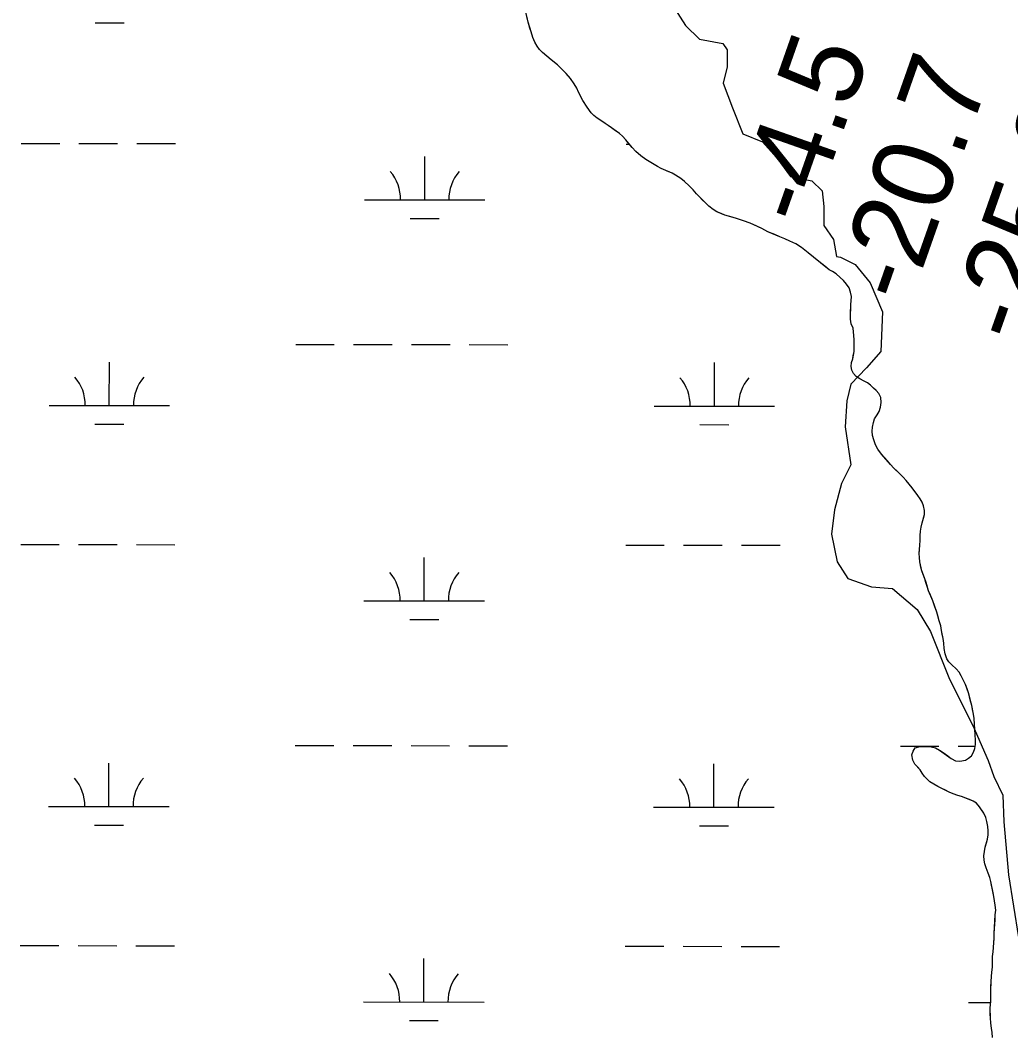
# Model space of a CAD drawing. Extents: x 3148686 to 3186545, y 916144 to 941516.
# Drawn here: x 3161687 to 3162509, y 935379 to 936220 of the extents above; entities that cross this region are included whole.
import ezdxf

# ---------------------------------------------------------------- set-up
doc = ezdxf.new("R2010")
doc.units = 0
for name, color, linetype in [('V-RIVR-EDGE', 7, 'Continuous'), ('V-RIVR-RANG', 7, 'Continuous'), ('V-SITE-VEGE', 7, 'Continuous'), ('V-WETL-SWMP', 7, 'Continuous')]:
    doc.layers.add(name, color=color, linetype=linetype)

msp = doc.modelspace()

# ---------------------------------------------------------------- linework, layer by layer
at = {"layer": 'V-RIVR-EDGE'}
for points in [[(3162222.05, 936242.3), (3162239.01, 936215.31), (3162250.68, 936203.93), (3162270.17, 936200.34), (3162273.71, 936195.01), (3162273.67, 936180.83), (3162270.45, 936167.36), (3162278.2, 936146.78)], [(3162278.2, 936146.78), (3162286.65, 936125.48), (3162302.95, 936118.7), (3162314.97, 936105.55), (3162326.28, 936089.92), (3162344, 936086.33), (3162352.49, 936078.15), (3162353.88, 936065.03), (3162353.84, 936049.43), (3162361.96, 936037.71), (3162364.41, 936023.52), (3162367.6, 936023.16), (3162380, 936017.1), (3162392.37, 936001.82), (3162402.59, 935977.68), (3162401.09, 935944.71), (3162389.36, 935931.26), (3162376.21, 935917.82), (3162372.98, 935904), (3162371.51, 935882.37), (3162376.4, 935850.8), (3162368.56, 935835.22), (3162362.83, 935813.6), (3162360.3, 935793.4), (3162364.85, 935770.34), (3162373.68, 935756.49), (3162393.52, 935749.7), (3162410.89, 935748.24), (3162431.42, 935730.81), (3162442.36, 935712.7), (3162458.22, 935672.95), (3162477.63, 935634.6), (3162490.32, 935605.49), (3162494.9, 935592.36), (3162502.31, 935576.74), (3162503.32, 935554.76), (3162507.11, 935510.78), (3162515.49, 935458.63)]]:
    msp.add_lwpolyline(points, dxfattribs=at)
at = {"layer": 'V-SITE-VEGE'}
for p, q in [((3162108.6, 936217.93), (3162106.4, 936227.37)), ((3162111.12, 936209.87), (3162108.6, 936217.93)), ((3162112.45, 936205.15), (3162111.12, 936209.87)), ((3162114.25, 936201.34), (3162112.45, 936205.15)), ((3162116.19, 936197.98), (3162114.25, 936201.34)), ((3162118.15, 936195.39), (3162116.19, 936197.98)), ((3162120.56, 936192.79), (3162118.15, 936195.39)), ((3162127.65, 936186.81), (3162120.56, 936192.79)), ((3162132.93, 936182.52), (3162127.65, 936186.81)), ((3162140.16, 936175.48), (3162132.93, 936182.52)), ((3162143.77, 936171.2), (3162140.16, 936175.48)), ((3162146.78, 936166.92), (3162143.77, 936171.2)), ((3162148.88, 936163.11), (3162146.78, 936166.92)), ((3162150.37, 936159.91), (3162148.88, 936163.11)), ((3162153.96, 936153.05), (3162150.37, 936159.91)), ((3162157.56, 936147.4), (3162153.96, 936153.05)), ((3162160.87, 936142.82), (3162157.56, 936147.4)), ((3162162.98, 936140.68), (3162160.87, 936142.82)), ((3162165.99, 936138.22), (3162162.98, 936140.68)), ((3162175.06, 936132.23), (3162165.99, 936138.22)), ((3162184.27, 936125.63), (3162175.06, 936132.23)), ((3162186.99, 936123.33), (3162184.27, 936125.63)), ((3162189.54, 936120.43), (3162186.99, 936123.33)), ((3162194.81, 936114.01), (3162189.54, 936120.43)), ((3162197.97, 936110.79), (3162194.81, 936114.01)), ((3162202.04, 936107.12), (3162197.97, 936110.79)), ((3162206.27, 936104.05), (3162202.04, 936107.12)), ((3162215.8, 936098.2), (3162206.27, 936104.05)), ((3162218.97, 936096.66), (3162215.8, 936098.2)), ((3162228.2, 936092.64), (3162218.97, 936096.66)), ((3162230.92, 936091.1), (3162228.2, 936092.64)), ((3162235.31, 936088.34), (3162230.92, 936091.1)), ((3162238.32, 936085.88), (3162235.31, 936088.34)), ((3162242.25, 936082.21), (3162238.32, 936085.88)), ((3162245.56, 936078.84), (3162242.25, 936082.21)), ((3162248.12, 936075.63), (3162245.56, 936078.84)), ((3162258.51, 936065.38), (3162248.12, 936075.63)), ((3162261.99, 936062.62), (3162258.51, 936065.38)), ((3162265.01, 936060.77), (3162261.99, 936062.62)), ((3162271.82, 936057.99), (3162265.01, 936060.77)), ((3162274.7, 936057.05), (3162271.82, 936057.99)), ((3162281.52, 936055.18), (3162274.7, 936057.05)), ((3162287.12, 936053.31), (3162281.52, 936055.18)), ((3162292.72, 936051.14), (3162287.12, 936053.31)), ((3162302.41, 936046.82), (3162292.72, 936051.14)), ((3162307.55, 936044.19), (3162302.41, 936046.82)), ((3162317.39, 936039.87), (3162307.55, 936044.19)), ((3162321.48, 936038.32), (3162317.39, 936039.87)), ((3162325.71, 936036.46), (3162321.48, 936038.32)), ((3162330.56, 936034.15), (3162325.71, 936036.46)), ((3162335.39, 936031.07), (3162330.56, 936034.15)), ((3162340.82, 936026.78), (3162335.39, 936031.07)), ((3162351.08, 936018.35), (3162340.82, 936026.78)), ((3162358.33, 936012.67), (3162351.08, 936018.35)), ((3162361.2, 936011.28), (3162358.33, 936012.67)), ((3162364.22, 936009.13), (3162361.2, 936011.28)), ((3162370.26, 936003.62), (3162364.22, 936009.13)), ((3162372.81, 936000.56), (3162370.26, 936003.62)), ((3162374.77, 935997.66), (3162372.81, 936000.56)), ((3162376.1, 935994.01), (3162374.77, 935997.66)), ((3162376.84, 935990.51), (3162376.1, 935994.01)), ((3162375.97, 935976.24), (3162376.32, 935983.38)), ((3162376.32, 935983.38), (3162376.84, 935990.51)), ((3162376.08, 935971.53), (3162375.97, 935976.24)), ((3162376.66, 935967.73), (3162376.08, 935971.53)), ((3162378.15, 935964.23), (3162376.66, 935967.73)), ((3162378.49, 935961.16), (3162378.15, 935964.23)), ((3162379, 935954.66), (3162378.49, 935961.16)), ((3162379.04, 935948.25), (3162379, 935954.66)), ((3162377.85, 935938.6), (3162378.92, 935944.82)), ((3162378.92, 935944.82), (3162379.04, 935948.25)), ((3162376.59, 935932.48), (3162376.81, 935935.64)), ((3162377.22, 935929.32), (3162376.59, 935932.48)), ((3162376.81, 935935.64), (3162377.85, 935938.6)), ((3162378.5, 935926.52), (3162377.22, 935929.32)), ((3162380.8, 935924.18), (3162378.5, 935926.52)), ((3162383.67, 935922.12), (3162380.8, 935924.18)), ((3162387.37, 935920.32), (3162383.67, 935922.12)), ((3162390.14, 935918.72), (3162387.37, 935920.32)), ((3162392.54, 935916.85), (3162390.14, 935918.72)), ((3162395.22, 935914.5), (3162392.54, 935916.85)), ((3162397.43, 935912.35), (3162395.22, 935914.5)), ((3162399.46, 935910.1), (3162397.43, 935912.35)), ((3162401.19, 935906.56), (3162399.46, 935910.1)), ((3162399.8, 935894.96), (3162400.95, 935898.58)), ((3162400.95, 935898.58), (3162401.54, 935902.47)), ((3162401.54, 935902.47), (3162401.19, 935906.56)), ((3162395.95, 935888.96), (3162398.02, 935892.38)), ((3162398.02, 935892.38), (3162399.8, 935894.96)), ((3162393.92, 935878.85), (3162394.22, 935882.1)), ((3162394.22, 935882.1), (3162395, 935885.99)), ((3162395, 935885.99), (3162395.95, 935888.96)), ((3162394.26, 935875.04), (3162393.92, 935878.85)), ((3162395.26, 935871.41), (3162394.26, 935875.04)), ((3162396.8, 935867.49), (3162395.26, 935871.41)), ((3162398.82, 935863.67), (3162396.8, 935867.49)), ((3162401.76, 935859.75), (3162398.82, 935863.67)), ((3162409.31, 935851.05), (3162401.76, 935859.75)), ((3162412.07, 935848.06), (3162409.31, 935851.05)), ((3162417.33, 935843.09), (3162412.07, 935848.06)), ((3162419.81, 935840.47), (3162417.33, 935843.09)), ((3162422.12, 935837.95), (3162419.81, 935840.47)), ((3162424.6, 935834.86), (3162422.12, 935837.95)), ((3162427.09, 935831.69), (3162424.6, 935834.86)), ((3162431.77, 935825.33), (3162427.09, 935831.69)), ((3162433.7, 935822.53), (3162431.77, 935825.33)), ((3162435.44, 935819.73), (3162433.7, 935822.53)), ((3162436.63, 935816.94), (3162435.44, 935819.73)), ((3162437.53, 935813.03), (3162436.63, 935816.94)), ((3162435.41, 935802.64), (3162437.32, 935809.5)), ((3162437.32, 935809.5), (3162437.53, 935813.03)), ((3162434.05, 935795.87), (3162434.63, 935799.21)), ((3162434.63, 935799.21), (3162435.41, 935802.64)), ((3162433.71, 935788.07), (3162433.74, 935792.07)), ((3162433.74, 935792.07), (3162434.05, 935795.87)), ((3162433.07, 935777.31), (3162433.4, 935784.08)), ((3162433.4, 935784.08), (3162433.71, 935788.07)), ((3162433.14, 935774.05), (3162433.07, 935777.31)), ((3162433.48, 935770.24), (3162433.14, 935774.05)), ((3162435.28, 935762.8), (3162433.48, 935770.24)), ((3162438.65, 935753.21), (3162435.28, 935762.8)), ((3162440.82, 935746.22), (3162438.65, 935753.21)), ((3162444.19, 935737.93), (3162440.82, 935746.22)), ((3162447.56, 935728.52), (3162444.19, 935737.93)), ((3162449.64, 935721.36), (3162447.56, 935728.52)), ((3162450.81, 935717.17), (3162449.64, 935721.36)), ((3162451.43, 935713.45), (3162450.81, 935717.17)), ((3162452.87, 935706.75), (3162451.43, 935713.45)), ((3162453.39, 935702.84), (3162452.87, 935706.75)), ((3162453.82, 935698.38), (3162453.39, 935702.84)), ((3162454.53, 935693.92), (3162453.82, 935698.38)), ((3162455.9, 935690.01), (3162454.53, 935693.92)), ((3162457.55, 935687.3), (3162455.9, 935690.01)), ((3162459.94, 935684.96), (3162457.55, 935687.3)), ((3162463.72, 935681.49), (3162459.94, 935684.96)), ((3162466.12, 935678.78), (3162463.72, 935681.49)), ((3162467.95, 935675.89), (3162466.12, 935678.78)), ((3162469.87, 935671.97), (3162467.95, 935675.89)), ((3162471.33, 935668.53), (3162469.87, 935671.97)), ((3162474.15, 935660.79), (3162471.33, 935668.53)), ((3162476.68, 935651.12), (3162474.15, 935660.79)), ((3162478.11, 935644.14), (3162476.68, 935651.12)), ((3162478.55, 935640.33), (3162478.11, 935644.14)), ((3162479.37, 935626.95), (3162478.55, 935640.33)), ((3162479.61, 935622.39), (3162479.37, 935626.95)), ((3162479.59, 935618.96), (3162479.61, 935622.39)), ((3162426.95, 935610.26), (3162428, 935613.32)), ((3162428, 935613.32), (3162429.78, 935616)), ((3162429.78, 935616), (3162432.67, 935616.91)), ((3162432.67, 935616.91), (3162439.54, 935617.13)), ((3162439.54, 935617.13), (3162442.79, 935617.01)), ((3162442.79, 935617.01), (3162446.59, 935615.96)), ((3162446.59, 935615.96), (3162449.83, 935614.27)), ((3162449.83, 935614.27), (3162459.62, 935607.32)), ((3162476.26, 935609.51), (3162478.14, 935612.47)), ((3162478.14, 935612.47), (3162479.19, 935615.43)), ((3162479.19, 935615.43), (3162479.59, 935618.96)), ((3162427.66, 935605.98), (3162426.95, 935610.26)), ((3162429.4, 935602.63), (3162427.66, 935605.98)), ((3162459.62, 935607.32), (3162463.14, 935605.43)), ((3162463.14, 935605.43), (3162466.76, 935605.12)), ((3162466.76, 935605.12), (3162471.4, 935605.83)), ((3162471.4, 935605.83), (3162473.93, 935607.48)), ((3162473.93, 935607.48), (3162476.26, 935609.51)), ((3162433.91, 935597.76), (3162429.4, 935602.63)), ((3162435.38, 935595.06), (3162433.91, 935597.76)), ((3162437.4, 935592.44), (3162435.38, 935595.06)), ((3162439.52, 935590.01), (3162437.4, 935592.44)), ((3162441.82, 935587.95), (3162439.52, 935590.01)), ((3162448.57, 935583.99), (3162441.82, 935587.95)), ((3162457.92, 935579.28), (3162448.57, 935583.99)), ((3162461.16, 935577.86), (3162457.92, 935579.28)), ((3162465.05, 935576.53), (3162461.16, 935577.86)), ((3162468.1, 935575.67), (3162465.05, 935576.53)), ((3162471.81, 935574.34), (3162468.1, 935575.67)), ((3162477.83, 935571.79), (3162471.81, 935574.34)), ((3162480.51, 935570.28), (3162477.83, 935571.79)), ((3162483.09, 935567.2), (3162480.51, 935570.28)), ((3162486.57, 935561.78), (3162483.09, 935567.2)), ((3162488.31, 935558.24), (3162486.57, 935561.78)), ((3162489.22, 935554.89), (3162488.31, 935558.24)), ((3162489.83, 935550.8), (3162489.22, 935554.89)), ((3162490.08, 935547.27), (3162489.83, 935550.8)), ((3162490.15, 935544.01), (3162490.08, 935547.27)), ((3162487.84, 935533.72), (3162489.75, 935540.3)), ((3162489.75, 935540.3), (3162490.15, 935544.01)), ((3162486.67, 935526.49), (3162487.07, 935530.11)), ((3162487.07, 935530.11), (3162487.84, 935533.72)), ((3162487.02, 935522.86), (3162486.67, 935526.49)), ((3162487.46, 935519.89), (3162487.02, 935522.86)), ((3162488.45, 935516.44), (3162487.46, 935519.89)), ((3162490.19, 935512.25), (3162488.45, 935516.44)), ((3162491.55, 935508.62), (3162490.19, 935512.25)), ((3162492.36, 935505.17), (3162491.55, 935508.62)), ((3162494.96, 935492.71), (3162492.36, 935505.17)), ((3162496.11, 935485.45), (3162494.96, 935492.71)), ((3162496.45, 935481.37), (3162496.11, 935485.45)), ((3162496.14, 935477.65), (3162496.45, 935481.37)), ((3162495.28, 935462.05), (3162496.14, 935477.65)), ((3162495.15, 935458.25), (3162495.28, 935462.05)), ((3162494.42, 935446.92), (3162495.15, 935458.25)), ((3162493.92, 935443.12), (3162494.42, 935446.92)), ((3162493.67, 935434.11), (3162493.9, 935439.96)), ((3162493.9, 935439.96), (3162493.92, 935443.12)), ((3162492.65, 935422.6), (3162493.17, 935430.12)), ((3162493.17, 935430.12), (3162493.67, 935434.11)), ((3162492.3, 935414.15), (3162492.65, 935422.6)), ((3162492.46, 935410.9), (3162492.3, 935414.15)), ((3162492.33, 935405.79), (3162492.46, 935410.9)), ((3162492.01, 935400.32), (3162492.33, 935405.79)), ((3162492.04, 935392.05), (3162492.01, 935400.32)), ((3162492.38, 935387.77), (3162492.04, 935392.05)), ((3162492.9, 935383.68), (3162492.38, 935387.77)), ((3162493.53, 935379.96), (3162492.9, 935383.68)), ((3162493.87, 935375.78), (3162493.53, 935379.96))]:
    msp.add_line(p, q, dxfattribs=at)
at = {"layer": 'V-WETL-SWMP'}
for p, q in [((3161749.49, 936217.34), (3161773.49, 936217.31)), ((3161687.98, 936117.4), (3161719.98, 936117.37)), ((3161735.98, 936117.35), (3161767.98, 936117.32)), ((3161783.98, 936117.3), (3161815.98, 936117.27)), ((3162189.88, 936116.87), (3162192.44, 936116.87)), ((3162022.77, 936070.62), (3162022.81, 936106.62)), ((3161972.77, 936070.67), (3162072.77, 936070.56)), ((3162010.76, 936055.2), (3162034.76, 936055.17)), ((3161915.8, 935950.66), (3161947.8, 935950.63)), ((3161963.8, 935950.61), (3161995.8, 935950.57)), ((3162011.8, 935950.56), (3162043.8, 935950.52)), ((3162059.8, 935950.51), (3162091.8, 935950.47)), ((3161761.16, 935900.08), (3161761.19, 935936.08)), ((3162263.06, 935899.55), (3162263.1, 935935.55)), ((3161711.16, 935900.13), (3161811.16, 935900.03)), ((3162213.06, 935899.6), (3162313.06, 935899.5)), ((3161749.14, 935884.66), (3161773.14, 935884.64)), ((3162251.05, 935884.13), (3162275.05, 935884.11)), ((3161687.63, 935784.73), (3161719.63, 935784.69)), ((3161735.63, 935784.67), (3161767.63, 935784.64)), ((3161783.63, 935784.62), (3161815.63, 935784.59)), ((3162189.53, 935784.2), (3162221.53, 935784.16)), ((3162237.53, 935784.15), (3162269.53, 935784.11)), ((3162285.53, 935784.1), (3162317.53, 935784.06)), ((3162022.42, 935737.94), (3162022.46, 935773.94)), ((3161972.42, 935738), (3162072.42, 935737.89)), ((3162010.4, 935722.52), (3162034.4, 935722.5)), ((3161915.45, 935617.98), (3161947.45, 935617.95)), ((3161963.45, 935617.93), (3161995.45, 935617.9)), ((3162011.45, 935617.88), (3162043.45, 935617.85)), ((3162059.45, 935617.83), (3162091.45, 935617.8)), ((3162417.36, 935617.46), (3162449.36, 935617.42)), ((3162465.36, 935617.4), (3162479.41, 935617.39)), ((3161760.8, 935567.4), (3161760.84, 935603.4)), ((3162262.71, 935566.88), (3162262.75, 935602.88)), ((3161710.8, 935567.46), (3161810.8, 935567.35)), ((3162212.71, 935566.93), (3162312.71, 935566.82)), ((3161748.79, 935551.99), (3161772.79, 935551.96)), ((3162250.7, 935551.46), (3162274.7, 935551.43)), ((3161687.28, 935452.05), (3161719.28, 935452.02)), ((3161735.28, 935452), (3161767.28, 935451.97)), ((3161783.28, 935451.95), (3161815.28, 935451.92)), ((3162189.18, 935451.52), (3162221.18, 935451.49)), ((3162237.18, 935451.47), (3162269.18, 935451.44)), ((3162285.18, 935451.42), (3162317.18, 935451.39)), ((3162022.07, 935405.27), (3162022.11, 935441.27)), ((3161972.07, 935405.32), (3162072.07, 935405.21)), ((3162473.98, 935404.79), (3162492.27, 935404.77)), ((3162010.05, 935389.85), (3162034.05, 935389.82))]:
    msp.add_line(p, q, dxfattribs=at)
msp.add_lwpolyline([(3162493.87, 935375.78), (3162493.53, 935379.96), (3162492.91, 935383.68), (3162492.38, 935387.77), (3162492.04, 935392.05), (3162491.97, 935395.3), (3162492.01, 935400.32), (3162492.33, 935405.79), (3162492.47, 935410.9), (3162492.31, 935414.15), (3162492.42, 935417.68), (3162492.65, 935422.6), (3162492.86, 935426.04), (3162493.17, 935430.12), (3162493.67, 935434.11), (3162493.9, 935439.96), (3162493.92, 935443.12), (3162494.42, 935446.92), (3162494.63, 935450.64), (3162494.84, 935454.07), (3162495.15, 935458.25), (3162495.28, 935462.05), (3162495.49, 935466.05), (3162495.71, 935469.95), (3162495.92, 935473.38), (3162496.14, 935477.65), (3162496.45, 935481.36), (3162496.11, 935485.45), (3162495.58, 935489.17), (3162494.96, 935492.71), (3162494.33, 935495.69), (3162493.7, 935498.66), (3162492.98, 935502.1), (3162492.36, 935505.17), (3162491.55, 935508.62), (3162490.19, 935512.25), (3162488.45, 935516.44), (3162487.46, 935519.89), (3162487.02, 935522.86), (3162486.67, 935526.49), (3162487.07, 935530.11), (3162487.84, 935533.72), (3162488.8, 935537.15), (3162489.75, 935540.3), (3162490.15, 935544.02), (3162490.08, 935547.27), (3162489.83, 935550.8), (3162489.21, 935554.89), (3162488.31, 935558.24), (3162486.57, 935561.78), (3162484.74, 935564.68), (3162483.09, 935567.2), (3162480.51, 935570.28), (3162477.83, 935571.79), (3162474.77, 935573.11), (3162471.81, 935574.34), (3162468.11, 935575.67), (3162465.05, 935576.53), (3162461.16, 935577.86), (3162457.92, 935579.28), (3162454.87, 935580.88), (3162451.81, 935582.3), (3162448.57, 935584), (3162445.15, 935586.07), (3162441.82, 935587.95), (3162439.52, 935590.01), (3162437.4, 935592.44), (3162435.38, 935595.06), (3162433.91, 935597.76), (3162431.61, 935600.2), (3162429.4, 935602.63), (3162427.66, 935605.98), (3162426.95, 935610.26), (3162428, 935613.32), (3162429.78, 935616), (3162432.67, 935616.91), (3162436.01, 935617.07), (3162439.54, 935617.13), (3162442.79, 935617.01), (3162446.59, 935615.96), (3162449.83, 935614.27), (3162452.78, 935612.2), (3162456.67, 935609.47), (3162459.62, 935607.32), (3162463.14, 935605.43), (3162466.75, 935605.12), (3162471.4, 935605.83), (3162473.93, 935607.48), (3162476.26, 935609.51), (3162478.14, 935612.47), (3162479.19, 935615.43), (3162479.59, 935618.96), (3162479.61, 935622.39), (3162479.37, 935626.95), (3162479.13, 935631.59), (3162478.79, 935636.05), (3162478.55, 935640.33), (3162478.11, 935644.14), (3162477.3, 935647.95), (3162476.68, 935651.12), (3162475.41, 935655.86), (3162474.15, 935660.79), (3162472.7, 935664.89), (3162471.33, 935668.53), (3162469.87, 935671.97), (3162467.95, 935675.89), (3162466.12, 935678.78), (3162463.72, 935681.5), (3162459.94, 935684.96), (3162457.55, 935687.3), (3162455.9, 935690.01), (3162454.53, 935693.92), (3162453.82, 935698.38), (3162453.39, 935702.84), (3162452.87, 935706.75), (3162452.15, 935710.38), (3162451.43, 935713.45), (3162450.81, 935717.17), (3162449.64, 935721.36), (3162448.64, 935724.71), (3162447.56, 935728.52), (3162445.92, 935733.09), (3162444.19, 935737.93), (3162442.28, 935742.78), (3162440.82, 935746.22), (3162439.73, 935749.85), (3162438.64, 935753.21), (3162437.65, 935756.19), (3162436.46, 935759.35), (3162435.28, 935762.8), (3162434.47, 935766.06), (3162433.48, 935770.24), (3162433.14, 935774.05), (3162433.07, 935777.31), (3162433.19, 935780.37), (3162433.4, 935784.08), (3162433.71, 935788.08), (3162433.74, 935792.07), (3162434.05, 935795.87), (3162434.64, 935799.21), (3162435.41, 935802.64), (3162436.55, 935806.54), (3162437.32, 935809.5), (3162437.53, 935813.03), (3162436.63, 935816.94), (3162435.44, 935819.73), (3162433.7, 935822.53), (3162431.77, 935825.33), (3162429.29, 935828.7), (3162427.08, 935831.69), (3162424.6, 935834.86), (3162422.12, 935837.95), (3162419.81, 935840.47), (3162417.33, 935843.09), (3162414.56, 935845.71), (3162412.07, 935848.06), (3162409.31, 935851.05), (3162406.64, 935854.04), (3162404.25, 935856.85), (3162401.76, 935859.75), (3162398.82, 935863.67), (3162396.8, 935867.49), (3162395.26, 935871.41), (3162394.26, 935875.04), (3162393.92, 935878.85), (3162394.22, 935882.1), (3162395, 935885.99), (3162395.95, 935888.96), (3162398.02, 935892.38), (3162399.8, 935894.96), (3162400.95, 935898.58), (3162401.53, 935902.47), (3162401.19, 935906.56), (3162399.46, 935910.1), (3162397.43, 935912.35), (3162395.22, 935914.5), (3162392.54, 935916.85), (3162390.14, 935918.72), (3162387.37, 935920.32), (3162383.67, 935922.12), (3162380.8, 935924.18), (3162378.5, 935926.52), (3162377.22, 935929.32), (3162376.6, 935932.48), (3162376.81, 935935.64), (3162377.85, 935938.6), (3162378.34, 935941.57), (3162378.92, 935944.82), (3162379.04, 935948.25), (3162379.06, 935951.5), (3162379, 935954.66), (3162378.74, 935958.01), (3162378.49, 935961.16), (3162378.15, 935964.23), (3162376.66, 935967.73), (3162376.08, 935971.53), (3162375.97, 935976.24), (3162376.15, 935980.04), (3162376.32, 935983.38), (3162376.66, 935987.17), (3162376.84, 935990.51), (3162376.1, 935994.01), (3162374.77, 935997.66), (3162372.81, 936000.56), (3162370.26, 936003.62), (3162367.54, 936006.07), (3162364.22, 936009.13), (3162361.2, 936011.28), (3162358.33, 936012.67), (3162355.76, 936014.67), (3162351.08, 936018.35), (3162345.35, 936023.1), (3162340.82, 936026.78), (3162335.39, 936031.07), (3162330.56, 936034.15), (3162325.71, 936036.46), (3162321.48, 936038.32), (3162317.39, 936039.87), (3162313.3, 936041.72), (3162307.55, 936044.19), (3162302.41, 936046.82), (3162297.72, 936048.98), (3162292.72, 936051.14), (3162287.12, 936053.31), (3162281.52, 936055.18), (3162277.73, 936056.27), (3162274.7, 936057.05), (3162271.82, 936057.99), (3162268.64, 936059.23), (3162265.01, 936060.77), (3162261.99, 936062.62), (3162258.52, 936065.38), (3162255.8, 936068.13), (3162253.09, 936070.73), (3162250.83, 936073.03), (3162248.12, 936075.63), (3162245.56, 936078.84), (3162242.25, 936082.21), (3162238.33, 936085.88), (3162235.31, 936088.34), (3162230.92, 936091.1), (3162228.2, 936092.64), (3162225.33, 936093.88), (3162218.97, 936096.66), (3162215.8, 936098.2), (3162211.87, 936100.67), (3162206.27, 936104.05), (3162202.04, 936107.12), (3162197.97, 936110.8), (3162194.81, 936114.01), (3162191.65, 936117.83), (3162189.54, 936120.43), (3162186.99, 936123.33), (3162184.27, 936125.63), (3162181.1, 936127.93), (3162177.62, 936130.39), (3162175.06, 936132.23), (3162172.49, 936133.92), (3162169.77, 936135.76), (3162165.99, 936138.22), (3162162.98, 936140.68), (3162160.87, 936142.82), (3162157.56, 936147.4), (3162153.96, 936153.05), (3162152.01, 936156.71), (3162150.37, 936159.91), (3162148.88, 936163.11), (3162146.78, 936166.92), (3162143.77, 936171.2), (3162140.16, 936175.48), (3162136.09, 936179.46), (3162132.93, 936182.52), (3162127.65, 936186.81), (3162124.03, 936189.88), (3162120.56, 936192.79), (3162118.15, 936195.39), (3162116.19, 936197.98), (3162114.25, 936201.34), (3162112.45, 936205.15), (3162111.12, 936209.87), (3162110.08, 936213.07), (3162108.6, 936217.93), (3162107.43, 936222.96)], dxfattribs=at)
for centre, start, end in [((3161967.53, 936071.15), 359.16781, 40.71147), ((3162078.01, 936071.03), 139.1678, 180.71146), ((3161705.91, 935900.61), 359.16781, 40.71147), ((3161816.4, 935900.5), 139.1678, 180.71146), ((3162207.82, 935900.08), 359.16781, 40.71147), ((3162318.31, 935899.97), 139.1678, 180.71146), ((3161967.18, 935738.48), 359.16781, 40.71147), ((3162077.66, 935738.36), 139.1678, 180.71146), ((3161705.56, 935567.94), 359.16781, 40.71147), ((3161816.05, 935567.82), 139.1678, 180.71146), ((3162207.47, 935567.41), 359.16781, 40.71147), ((3162317.96, 935567.29), 139.1678, 180.71146), ((3161966.83, 935405.8), 359.16781, 40.71147), ((3162077.31, 935405.68), 139.1678, 180.71146)]:
    msp.add_arc(centre, 35.25, start, end, dxfattribs=at)

# ---------------------------------------------------------------- texts
at = {"layer": 'V-RIVR-RANG'}
for s, p in [('-4.5', (3162341.46, 936046.33)), ('-20.7', (3162424.85, 935982.03)), ('-25.9', (3162519.18, 935948.85))]:
    msp.add_text(s, height=67, rotation=70.62833, dxfattribs=at).set_placement(p)

doc.saveas('drawing.dxf')
